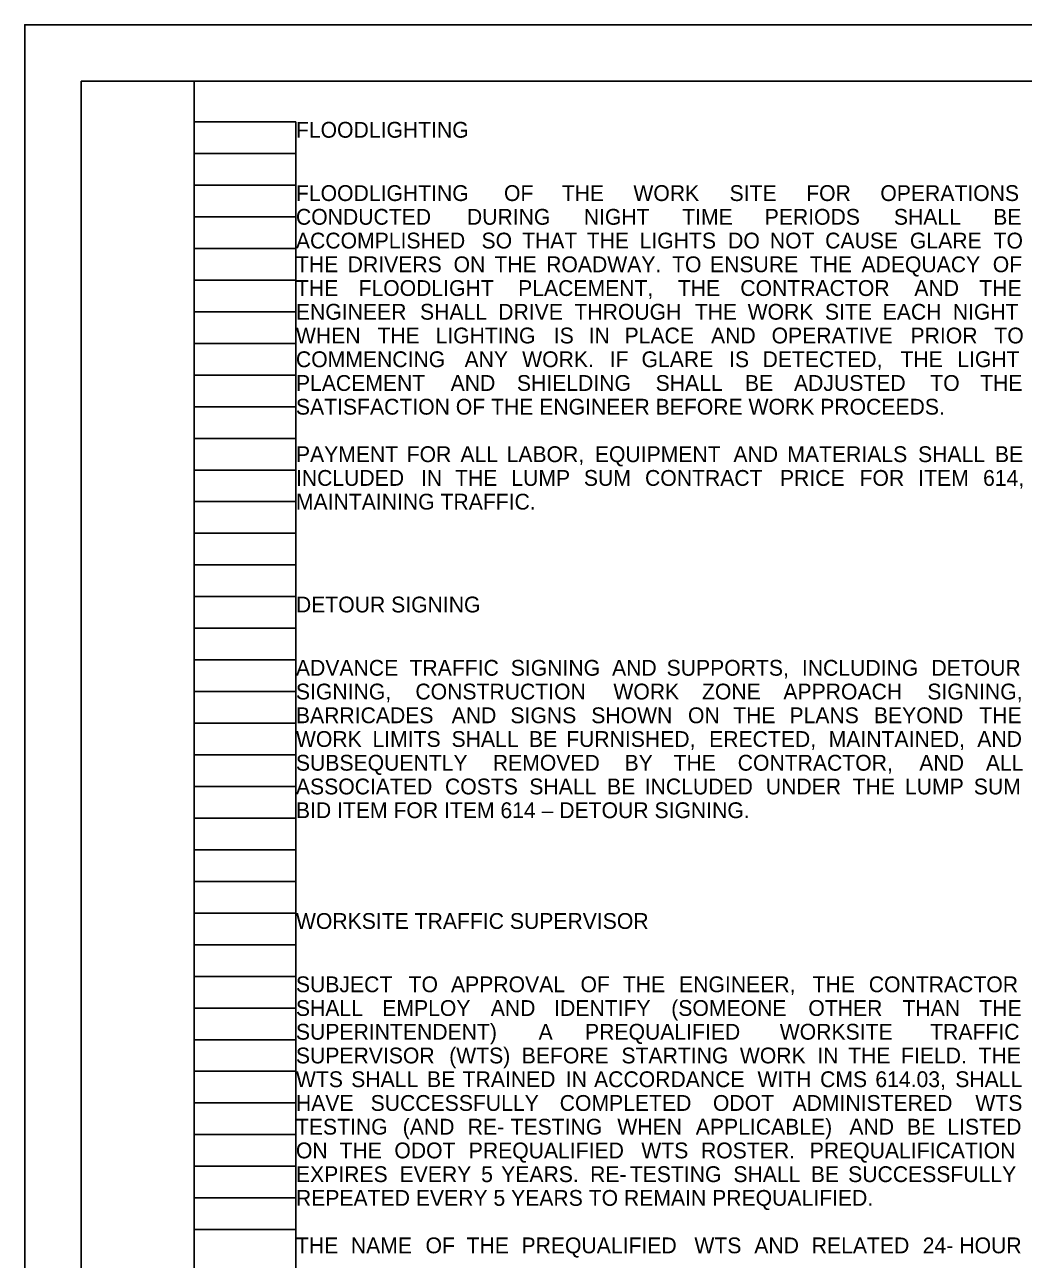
# Model space of a CAD drawing. Extents: x 0 to 34, y 0 to 22.
# Drawn here: x 0 to 8.84, y 11.08 to 22 of the extents above; entities that cross this region are included whole.
import ezdxf

# ---------------------------------------------------------------- set-up
doc = ezdxf.new("R2010")
doc.units = 0
for name, color, linetype in [('SH_Border', 7, 'Continuous'), ('SH_Cut_Line', 7, 'Continuous'), ('SH_Data', 7, 'Continuous'), ('SH_Text', 7, 'Continuous')]:
    doc.layers.add(name, color=color, linetype=linetype)

msp = doc.modelspace()

# ---------------------------------------------------------------- linework, layer by layer
at = {"layer": 'SH_Border'}
for points in [[(0.5, 21.5), (1.5, 21.5), (1.5, 0.5), (0.5, 0.5)], [(1.5, 21.5), (33.5, 21.5), (33.5, 0.5), (1.5, 0.5)]]:
    msp.add_lwpolyline(points, close=True, dxfattribs=at)
at = {"layer": 'SH_Cut_Line'}
msp.add_lwpolyline([(0, 0), (34, 0), (34, 22), (0, 22)], close=True, dxfattribs=at)
at = {"layer": 'SH_Data'}
for p, q in [((1.5, 0.98), (1.5, 21.14)), ((1.5, 21.14), (2.4, 21.14)), ((2.4, 0.98), (2.4, 21.14)), ((1.5, 20.86), (2.4, 20.86)), ((1.5, 20.58), (2.4, 20.58)), ((1.5, 20.3), (2.4, 20.3)), ((1.5, 20.02), (2.4, 20.02)), ((1.5, 19.74), (2.4, 19.74)), ((1.5, 19.46), (2.4, 19.46)), ((1.5, 19.18), (2.4, 19.18)), ((1.5, 18.9), (2.4, 18.9)), ((1.5, 18.62), (2.4, 18.62)), ((1.5, 18.34), (2.4, 18.34)), ((1.5, 18.06), (2.4, 18.06)), ((1.5, 17.78), (2.4, 17.78)), ((1.5, 17.5), (2.4, 17.5)), ((1.5, 17.22), (2.4, 17.22)), ((1.5, 16.94), (2.4, 16.94)), ((1.5, 16.66), (2.4, 16.66)), ((1.5, 16.38), (2.4, 16.38)), ((1.5, 16.1), (2.4, 16.1)), ((1.5, 15.82), (2.4, 15.82)), ((1.5, 15.54), (2.4, 15.54)), ((1.5, 15.26), (2.4, 15.26)), ((1.5, 14.98), (2.4, 14.98)), ((1.5, 14.7), (2.4, 14.7)), ((1.5, 14.42), (2.4, 14.42)), ((1.5, 14.14), (2.4, 14.14)), ((1.5, 13.86), (2.4, 13.86)), ((1.5, 13.58), (2.4, 13.58)), ((1.5, 13.3), (2.4, 13.3)), ((1.5, 13.02), (2.4, 13.02)), ((1.5, 12.74), (2.4, 12.74)), ((1.5, 12.46), (2.4, 12.46)), ((1.5, 12.18), (2.4, 12.18)), ((1.5, 11.9), (2.4, 11.9)), ((1.5, 11.62), (2.4, 11.62)), ((1.5, 11.34), (2.4, 11.34))]:
    msp.add_line(p, q, dxfattribs=at)

# ---------------------------------------------------------------- texts
at = {"layer": 'SH_Text'}
for s, p in [('FLOODLIGHTING', (2.4, 21)), ('FLOODLIGHTING ', (2.4, 20.44)), ('OF ', (4.241, 20.44)), ('THE ', (4.752, 20.44)), ('WORK ', (5.386, 20.44)), ('SITE ', (6.237, 20.44)), ('FOR ', (6.915, 20.44)), ('OPERATIONS ', (7.571, 20.44)), ('CONDUCTED ', (2.4, 20.23)), ('DURING ', (3.913, 20.23)), ('NIGHT ', (4.947, 20.23)), ('TIME ', (5.818, 20.23)), ('PERIODS ', (6.548, 20.23)), ('SHALL ', (7.691, 20.23)), ('BE ', (8.57, 20.23)), ('ACCOMPLISHED ', (2.4, 20.02)), ('SO ', (4.042, 20.02)), ('THAT ', (4.401, 20.02)), ('THE ', (4.973, 20.02)), ('LIGHTS ', (5.441, 20.02)), ('DO ', (6.224, 20.02)), ('NOT ', (6.594, 20.02)), ('CAUSE ', (7.083, 20.02)), ('GLARE ', (7.833, 20.02)), ('TO ', (8.573, 20.02)), ('THE ', (2.4, 19.81)), ('DRIVERS ', (2.858, 19.81)), ('ON ', (3.795, 19.81)), ('THE ', (4.156, 19.81)), ('ROADWAY. ', (4.614, 19.81)), ('TO ', (5.728, 19.81)), ('ENSURE ', (6.064, 19.81)), ('THE ', (6.946, 19.81)), ('ADEQUACY ', (7.404, 19.81)), ('OF ', (8.566, 19.81)), ('THE ', (2.4, 19.6)), ('FLOODLIGHT ', (2.954, 19.6)), ('PLACEMENT, ', (4.366, 19.6)), ('THE ', (5.779, 19.6)), ('CONTRACTOR ', (6.332, 19.6)), ('AND ', (7.872, 19.6)), ('THE ', (8.447, 19.6)), ('ENGINEER ', (2.4, 19.39)), ('SHALL ', (3.498, 19.39)), ('DRIVE ', (4.19, 19.39)), ('THROUGH ', (4.864, 19.39)), ('THE ', (5.929, 19.39)), ('WORK ', (6.397, 19.39)), ('SITE ', (7.081, 19.39)), ('EACH ', (7.592, 19.39)), ('NIGHT ', (8.212, 19.39)), ('WHEN ', (2.4, 19.18)), ('THE ', (3.121, 19.18)), ('LIGHTING ', (3.635, 19.18)), ('IS ', (4.682, 19.18)), ('IN ', (4.99, 19.18)), ('PLACE ', (5.308, 19.18)), ('AND ', (6.073, 19.18)), ('OPERATIVE ', (6.609, 19.18)), ('PRIOR ', (7.838, 19.18)), ('TO ', (8.58, 19.18)), ('COMMENCING ', (2.4, 18.97)), ('ANY ', (3.892, 18.97)), ('WORK. ', (4.402, 18.97)), ('IF ', (5.176, 18.97)), ('GLARE ', (5.458, 18.97)), ('IS ', (6.233, 18.97)), ('DETECTED, ', (6.529, 18.97)), ('THE ', (7.749, 18.97)), ('LIGHT ', (8.252, 18.97)), ('PLACEMENT ', (2.4, 18.76)), ('AND ', (3.769, 18.76)), ('SHIELDING ', (4.355, 18.76)), ('SHALL ', (5.583, 18.76)), ('BE ', (6.373, 18.76)), ('ADJUSTED ', (6.807, 18.76)), ('TO ', (8.013, 18.76)), ('THE ', (8.454, 18.76)), ('SATISFACTION OF THE ENGINEER BEFORE WORK PROCEEDS.', (2.4, 18.55)), ('PAYMENT ', (2.4, 18.13)), ('FOR ', (3.38, 18.13)), ('ALL ', (3.856, 18.13)), ('LABOR, ', (4.264, 18.13)), ('EQUIPMENT ', (5.045, 18.13)), ('AND ', (6.271, 18.13)), ('MATERIALS ', (6.748, 18.13)), ('SHALL ', (7.905, 18.13)), ('BE ', (8.585, 18.13)), ('INCLUDED ', (2.4, 17.92)), ('IN ', (3.506, 17.92)), ('THE ', (3.808, 17.92)), ('LUMP ', (4.306, 17.92)), ('SUM ', (4.948, 17.92)), ('CONTRACT ', (5.489, 17.92)), ('PRICE ', (6.683, 17.92)), ('FOR ', (7.387, 17.92)), ('ITEM ', (7.906, 17.92)), ('614, ', (8.48, 17.92)), ('MAINTAINING TRAFFIC.', (2.4, 17.71)), ('DETOUR SIGNING', (2.4, 16.8)), ('ADVANCE ', (2.4, 16.24)), ('TRAFFIC ', (3.405, 16.24)), ('SIGNING ', (4.301, 16.24)), ('AND ', (5.197, 16.24)), ('SUPPORTS, ', (5.68, 16.24)), ('INCLUDING ', (6.877, 16.24)), ('DETOUR ', (8.023, 16.24)), ('SIGNING, ', (2.4, 16.03)), ('CONSTRUCTION ', (3.457, 16.03)), ('WORK ', (5.209, 16.03)), ('ZONE ', (5.993, 16.03)), ('APPROACH ', (6.713, 16.03)), ('SIGNING, ', (7.987, 16.03)), ('BARRICADES ', (2.4, 15.82)), ('AND ', (3.778, 15.82)), ('SIGNS ', (4.298, 15.82)), ('SHOWN ', (5.013, 15.82)), ('ON ', (5.869, 15.82)), ('THE ', (6.269, 15.82)), ('PLANS ', (6.767, 15.82)), ('BEYOND ', (7.514, 15.82)), ('THE ', (8.447, 15.82)), ('WORK ', (2.4, 15.61)), ('LIMITS ', (3.077, 15.61)), ('SHALL ', (3.777, 15.61)), ('BE ', (4.462, 15.61)), ('FURNISHED, ', (4.791, 15.61)), ('ERECTED, ', (6.056, 15.61)), ('MAINTAINED, ', (7.114, 15.61)), ('AND ', (8.429, 15.61)), ('SUBSEQUENTLY ', (2.4, 15.4)), ('REMOVED ', (4.142, 15.4)), ('BY ', (5.308, 15.4)), ('THE ', (5.741, 15.4)), ('CONTRACTOR, ', (6.309, 15.4)), ('AND ', (7.916, 15.4)), ('ALL ', (8.505, 15.4)), ('ASSOCIATED ', (2.4, 15.19)), ('COSTS ', (3.719, 15.19)), ('SHALL ', (4.465, 15.19)), ('BE ', (5.153, 15.19)), ('INCLUDED ', (5.486, 15.19)), ('UNDER ', (6.558, 15.19)), ('THE ', (7.326, 15.19)), ('LUMP ', (7.789, 15.19)), ('SUM ', (8.398, 15.19)), ('BID ITEM FOR ITEM 614 – DETOUR SIGNING.', (2.4, 14.98)), ('WORKSITE TRAFFIC SUPERVISOR', (2.4, 14)), ('SUBJECT ', (2.4, 13.44)), ('TO ', (3.397, 13.44)), ('APPROVAL ', (3.772, 13.44)), ('OF ', (4.918, 13.44)), ('THE ', (5.292, 13.44)), ('ENGINEER, ', (5.79, 13.44)), ('THE ', (6.972, 13.44)), ('CONTRACTOR ', (7.469, 13.44)), ('SHALL ', (2.4, 13.23)), ('EMPLOY ', (3.164, 13.23)), ('AND ', (4.124, 13.23)), ('IDENTIFY ', (4.685, 13.23)), ('(SOMEONE ', (5.721, 13.23)), ('OTHER ', (6.934, 13.23)), ('THAN ', (7.767, 13.23)), ('THE ', (8.447, 13.23)), ('SUPERINTENDENT) ', (2.4, 13.02)), ('A ', (4.547, 13.02)), ('PREQUALIFIED ', (4.958, 13.02)), ('WORKSITE ', (6.681, 13.02)), ('TRAFFIC ', (8.012, 13.02)), ('SUPERVISOR ', (2.4, 12.81)), ('(WTS) ', (3.756, 12.81)), ('BEFORE ', (4.398, 12.81)), ('STARTING ', (5.28, 12.81)), ('WORK ', (6.328, 12.81)), ('IN ', (7.013, 12.81)), ('THE ', (7.286, 12.81)), ('FIELD. ', (7.754, 12.81)), ('THE ', (8.44, 12.81)), ('WTS ', (2.4, 12.6)), ('SHALL ', (2.889, 12.6)), ('BE ', (3.56, 12.6)), ('TRAINED ', (3.875, 12.6)), ('IN ', (4.788, 12.6)), ('ACCORDANCE ', (5.038, 12.6)), ('WITH ', (6.484, 12.6)), ('CMS ', (7.038, 12.6)), ('614.03, ', (7.527, 12.6)), ('SHALL ', (8.234, 12.6)), ('HAVE ', (2.4, 12.39)), ('SUCCESSFULLY ', (3.061, 12.39)), ('COMPLETED ', (4.734, 12.39)), ('ODOT ', (6.09, 12.39)), ('ADMINISTERED ', (6.794, 12.39)), ('WTS ', (8.412, 12.39)), ('TESTING ', (2.4, 12.18)), ('(AND ', (3.345, 12.18)), ('RE-', (3.92, 12.18)), ('TESTING ', (4.299, 12.18)), ('WHEN ', (5.244, 12.18)), ('APPLICABLE) ', (5.938, 12.18)), ('AND ', (7.297, 12.18)), ('BE ', (7.807, 12.18)), ('LISTED ', (8.164, 12.18)), ('ON ', (2.4, 11.97)), ('THE ', (2.786, 11.97)), ('ODOT ', (3.271, 11.97)), ('PREQUALIFIED ', (3.929, 11.97)), ('WTS ', (5.456, 11.97)), ('ROSTER. ', (5.984, 11.97)), ('PREQUALIFICATION ', (6.946, 11.97)), ('EXPIRES ', (2.4, 11.76)), ('EVERY ', (3.317, 11.76)), ('5 ', (4.039, 11.76)), ('YEARS. ', (4.216, 11.76)), ('RE-', (5.003, 11.76)), ('TESTING ', (5.354, 11.76)), ('SHALL ', (6.271, 11.76)), ('BE ', (6.956, 11.76)), ('SUCCESSFULLY ', (7.286, 11.76)), ('REPEATED EVERY 5 YEARS TO REMAIN PREQUALIFIED.', (2.4, 11.55)), ('THE ', (2.4, 11.13)), ('NAME ', (2.886, 11.13)), ('OF ', (3.547, 11.13)), ('THE ', (3.91, 11.13)), ('PREQUALIFIED ', (4.396, 11.13)), ('WTS ', (5.926, 11.13)), ('AND ', (6.456, 11.13)), ('RELATED ', (6.964, 11.13)), ('24-', (7.946, 11.13)), ('HOUR ', (8.27, 11.13))]:
    msp.add_text(s, height=0.14, dxfattribs=at).set_placement(p)

doc.saveas('drawing.dxf')
